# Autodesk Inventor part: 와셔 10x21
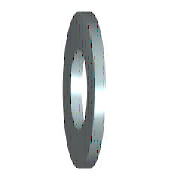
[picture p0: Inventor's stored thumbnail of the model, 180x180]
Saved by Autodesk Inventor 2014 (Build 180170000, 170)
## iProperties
Created: 2012-02
Part Number: 와셔 10x21
Material: 강철, 연강
Description: 평면 와셔
Document SubType Name: Modeling
Standard: KS B 1326
Designer: mduedu
Standards Organization: KS
Language: ko-KR
Size Designation: 10x21
Categories: <MemberInstance><Categories><Category DisplayName="조임쇠" InternalName="e4da775c-781d-43d5-af7c-5136215cf5a6" Mnemonic="FSTN"><Category DisplayName="와셔" InternalN
Density: 1 g/cm^3
Appearance: 파란색 - 벽 페인트 - 광택
IsCustomPart: 1
Author: mduedu
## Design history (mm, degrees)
sketch "스케치"
  geometry: C1 r 10.5 at (0, 0); C2 r 5.25 at (0, 0); 1 further point
  constraints: 2 centre point, 2 coincident
  dimensions: "d0" = 10.5 diameter of C2 (= SD1); "d1" = 21 diameter of C1 (= SD2)
extrude "본체" new body sketch "스케치" distance "d2" = 2 (= SD); taper "d3" = 0 deg
workaxis "Work Axis1"
workplane "Work Plane1"
body "Solid1"
other parameters: "SD1" = 10.5 [user parameter; used in 1 equation term], "SD2" = 21 [user parameter; used in 1 equation term], "SD" = 2 [user parameter; used in 1 equation term], "d4" = 0, "d5" = 0, "d6" = 0, "d7" = 0
